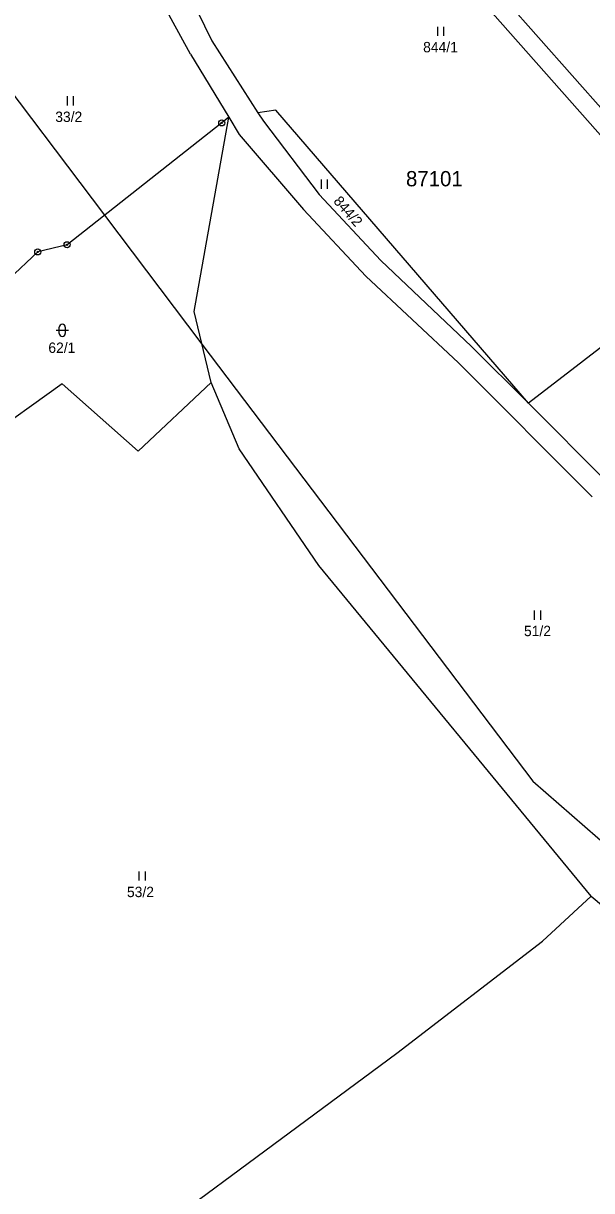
# Model space of a CAD drawing. Extents: x -547623 to -538651, y -1096714 to -1086522.
# Drawn here: x -539837.5 to -539744.3, y -1092647.6 to -1092456.3 of the extents above; entities that cross this region are included whole.
import ezdxf

# ---------------------------------------------------------------- set-up
doc = ezdxf.new("R2010")
doc.units = 0
for name, color, linetype in [('Vrstva 1', 7, 'Continuous'), ('Vrstva 25', 7, 'Continuous'), ('Vrstva 30', 7, 'Continuous'), ('Vrstva 52', 7, 'Continuous'), ('Vrstva 53', 7, 'Continuous'), ('Vrstva 83', 7, 'Continuous'), ('Vrstva 86', 7, 'Continuous')]:
    doc.layers.add(name, color=color, linetype=linetype)

msp = doc.modelspace()

# ---------------------------------------------------------------- linework, layer by layer
at = {"layer": 'Vrstva 1'}
for points in [[(-539814.87, -1092442.16), (-539806.58, -1092459.23)], [(-539810.06, -1092461.37), (-539814.84, -1092452.73)], [(-539806.58, -1092459.23), (-539799.03, -1092470.99)], [(-539810.06, -1092461.37), (-539803.79, -1092471.73)], [(-539796.12, -1092470.54), (-539799.03, -1092470.99)], [(-539754.72, -1092518.57), (-539796.12, -1092470.54)], [(-539809.46, -1092503.55), (-539803.79, -1092471.73)], [(-539803.79, -1092471.73), (-539804.96, -1092472.65)], [(-539803.79, -1092471.73), (-539802.09, -1092474.53)], [(-539799.03, -1092470.99), (-539798.14, -1092472.38)], [(-539798.14, -1092472.38), (-539789.01, -1092484.38)], [(-539804.96, -1092472.65), (-539830.3, -1092492.62)], [(-539802.09, -1092474.53), (-539791.55, -1092486.83)], [(-539789.01, -1092484.38), (-539778.88, -1092495.17)], [(-539791.55, -1092486.83), (-539781.34, -1092497.76)], [(-539830.3, -1092492.62), (-539835.1, -1092493.79)], [(-539835.1, -1092493.79), (-539839.84, -1092498.24)], [(-539764.03, -1092509.26), (-539778.88, -1092495.17)], [(-539766.17, -1092511.96), (-539781.34, -1092497.76)], [(-539727.65, -1092497.74), (-539754.72, -1092518.57)], [(-539806.7, -1092515.2), (-539809.46, -1092503.55)], [(-539754.72, -1092518.57), (-539764.03, -1092509.26)], [(-539744.25, -1092533.91), (-539766.17, -1092511.96)], [(-539831.12, -1092515.38), (-539844.08, -1092524.7)], [(-539818.66, -1092526.45), (-539831.12, -1092515.38)], [(-539806.7, -1092515.2), (-539818.66, -1092526.45)], [(-539802.1, -1092526.06), (-539806.7, -1092515.2)], [(-539741.87, -1092531.43), (-539754.72, -1092518.57)], [(-539789.03, -1092545.14), (-539802.1, -1092526.06)], [(-539744.44, -1092599.31), (-539789.03, -1092545.14)], [(-539752.41, -1092606.68), (-539744.44, -1092599.31)], [(-539744.44, -1092599.31), (-539717.57, -1092621.81)], [(-539776.28, -1092625.06), (-539752.41, -1092606.68)], [(-539834.45, -1092668.08), (-539776.28, -1092625.06)]]:
    msp.add_lwpolyline(points, dxfattribs=at)
at = {"layer": 'Vrstva 25'}
for p, q in [((-539769.55, -1092458.39), (-539769.55, -1092456.89)), ((-539768.55, -1092458.39), (-539768.55, -1092456.89)), ((-539830.23, -1092469.8), (-539830.23, -1092468.3)), ((-539829.23, -1092469.8), (-539829.23, -1092468.3)), ((-539788.61, -1092483.45), (-539788.61, -1092481.95)), ((-539787.61, -1092483.45), (-539787.61, -1092481.95)), ((-539832.09, -1092506.63), (-539830.09, -1092506.63)), ((-539831.59, -1092507.13), (-539831.59, -1092506.13)), ((-539830.59, -1092506.13), (-539830.59, -1092507.13)), ((-539753.69, -1092554.03), (-539753.69, -1092552.53)), ((-539752.69, -1092554.03), (-539752.69, -1092552.53)), ((-539818.48, -1092596.78), (-539818.48, -1092595.28)), ((-539817.48, -1092596.78), (-539817.48, -1092595.28))]:
    msp.add_line(p, q, dxfattribs=at)
for centre, start, end in [((-539831.09, -1092506.13), 0, 180), ((-539831.09, -1092507.13), 180, 0)]:
    msp.add_arc(centre, 0.5, start, end, dxfattribs=at)
at = {"layer": 'Vrstva 30'}
for points in [[(-539758.57, -1092452.41), (-539725.5, -1092489.77)], [(-539727.75, -1092491.76), (-539760.59, -1092454.66)]]:
    msp.add_lwpolyline(points, dxfattribs=at)
at = {"layer": 'Vrstva 52'}
msp.add_lwpolyline([(-539911.5, -1092362), (-539906.38, -1092370.45), (-539898.01, -1092384.26), (-539889.98, -1092397.52), (-539886.91, -1092402.59), (-539880, -1092414), (-539879.9, -1092414.13), (-539844.26, -1092461.23), (-539824.16, -1092487.78), (-539808.2, -1092508.88), (-539754, -1092580.5), (-539709.23, -1092619.45), (-539642.5, -1092677.5), (-539608.53, -1092701.71), (-539605.85, -1092703.62), (-539548.9, -1092744.22), (-539548.5, -1092744.5), (-539431, -1092815)], dxfattribs=at)
at = {"layer": 'Vrstva 83'}
for centre, radius in [((-539804.96, -1092472.65), 0.5), ((-539804.96, -1092472.65), 0.1), ((-539835.1, -1092493.79), 0.5), ((-539830.3, -1092492.62), 0.5), ((-539830.3, -1092492.62), 0.1), ((-539835.1, -1092493.79), 0.1)]:
    msp.add_circle(centre, radius, dxfattribs=at)

# ---------------------------------------------------------------- texts
at = {"layer": 'Vrstva 53'}
msp.add_text('87101', height=2.5, dxfattribs=at).set_placement((-539774.77, -1092483.04))
at = {"layer": 'Vrstva 86'}
for s, p in [('844/1', (-539771.96, -1092461.09)), ('33/2', (-539832.24, -1092472.5)), ('62/1', (-539833.37, -1092510.33)), ('51/2', (-539755.43, -1092556.73)), ('53/2', (-539820.49, -1092599.48))]:
    msp.add_text(s, height=1.7, dxfattribs=at).set_placement(p)
msp.add_text('844/2', height=1.7, rotation=311.2671, dxfattribs=at).set_placement((-539786.76, -1092485.55))

doc.saveas('drawing.dxf')
